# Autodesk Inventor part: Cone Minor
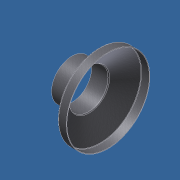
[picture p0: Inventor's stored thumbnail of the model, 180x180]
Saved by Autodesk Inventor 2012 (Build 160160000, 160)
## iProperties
Category: Mechanical Engineering Drawing and Design - CADD
Manager: Fábio Ricardo de Oliveira Souza
Company: SENAI - Serviço Nacional de Aprendizagem Industrial
Created: 2011-06
Part Number: Cone Minor
Material: Steel
Description: Stainless Steel (DIN- X6CrNiTi18-10)
Document SubType Name: Modeling
Designer: Guilherme Augusto Franco de Souza
Engineer: George Geraldo de Oliveia Silva
Authority: Fábio Ricardo de Oliveira Soza
Density: 7.85 g/cm^3
Subject: WorldSkill 2011 - London, England
Author: Guilherme Augusto Franco de Souza
Revision Number: 00
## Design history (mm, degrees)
sketch "Sketch2"
  geometry: L1 (0, 0)-(65, 0); L2 (65, 0)-(65, 75); L3 (65, 75)-(50, 75); L4 (50, 75)-(30, 36.45); L5 (30, 36.45)-(0, 36.45); L6 (0, 36.45)-(0, 0)
  constraints: 12 end point, 3 parallel, 1 horizontal, 1 perpendicular
  dimensions: "Diam_menor" = 72.9 diameter of L5 L1; "Diam_maior" = 150 diameter of L3 L1; "d4" = 30 distance of L4.end L5.end; "d5" = 15 distance of L2.end L3.end; "Comp_cone" = 20 horizontal distance of L3.end L4.end
revolve "Revolution1" sketch "Sketch2" stored, may be unused: angle "d7" = 90 deg
fillet "Fillet1" dims "d8" = 1, "d10" = 2
shell "Shell1" dims "d9" = 1
body "Solid2"
